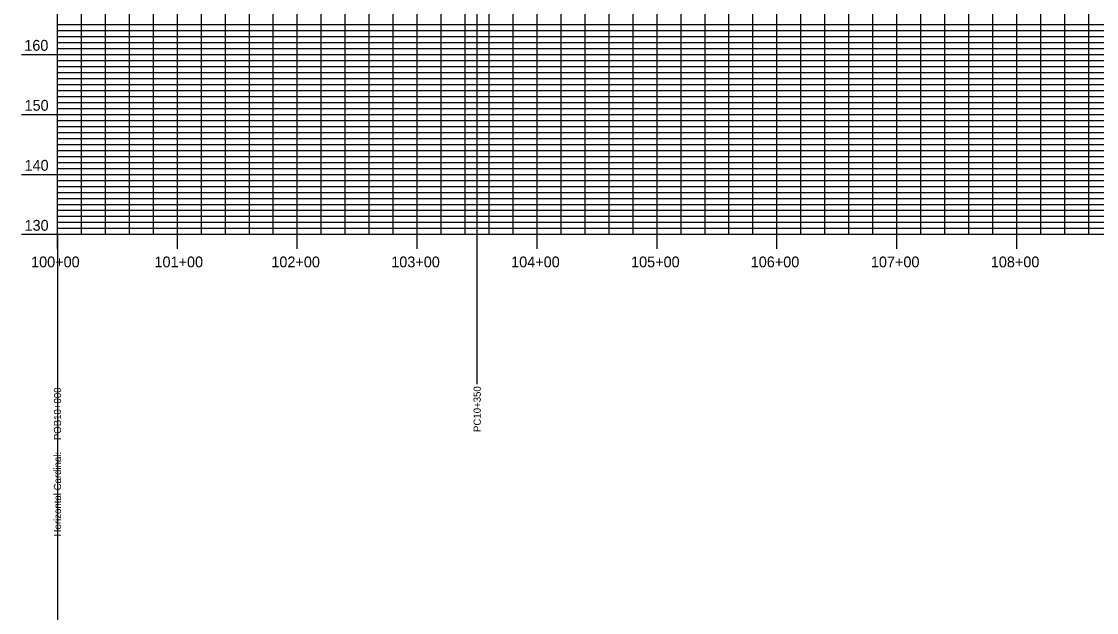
# Model space of a CAD drawing. Extents: x 1451449 to 1456010, y 297581 to 299758.
# Drawn here: x 1451450 to 1452346, y 298638 to 299131 of the extents above; entities that cross this region are included whole.
import ezdxf

# ---------------------------------------------------------------- set-up
doc = ezdxf.new("R2010")
doc.units = 0
for name, color, linetype in [('51', 7, 'Continuous'), ('Grid', 7, 'Continuous'), ('Grid_Labels', 7, 'Continuous'), ('Grid_Major', 7, 'Continuous'), ('Grid_Minor', 7, 'Continuous'), ('PCPT', 7, 'Continuous'), ('PRF_Bridge', 7, 'Continuous')]:
    doc.layers.add(name, color=color, linetype=linetype)

msp = doc.modelspace()

# ---------------------------------------------------------------- linework, layer by layer
at = {"layer": 'Grid'}
for p, q in [((1451829.67, 298828.55), (1451829.67, 299695.92)), ((1451479.67, 298953.55), (1451479.67, 299553.55)), ((1451479.67, 299128.55), (1451482.67, 299128.55)), ((1451479.67, 299123.55), (1451482.67, 299123.55)), ((1451479.67, 299118.55), (1451482.67, 299118.55)), ((1451479.67, 299113.55), (1451482.67, 299113.55)), ((1451479.67, 299108.55), (1451482.67, 299108.55)), ((1451449.67, 299103.55), (1451479.67, 299103.55)), ((1451479.67, 299098.55), (1451482.67, 299098.55)), ((1451479.67, 299093.55), (1451482.67, 299093.55)), ((1451479.67, 299088.55), (1451482.67, 299088.55)), ((1451479.67, 299083.55), (1451482.67, 299083.55)), ((1451479.67, 299078.55), (1451482.67, 299078.55)), ((1451479.67, 299073.55), (1451482.67, 299073.55)), ((1451479.67, 299068.55), (1451482.67, 299068.55)), ((1451479.67, 299063.55), (1451482.67, 299063.55)), ((1451449.67, 299053.55), (1451479.67, 299053.55)), ((1451479.67, 299058.55), (1451482.67, 299058.55)), ((1451479.67, 299048.55), (1451482.67, 299048.55)), ((1451479.67, 299043.55), (1451482.67, 299043.55)), ((1451479.67, 299038.55), (1451482.67, 299038.55)), ((1451479.67, 299033.55), (1451482.67, 299033.55)), ((1451479.67, 299028.55), (1451482.67, 299028.55)), ((1451479.67, 299023.55), (1451482.67, 299023.55)), ((1451479.67, 299018.55), (1451482.67, 299018.55)), ((1451479.67, 299013.55), (1451482.67, 299013.55)), ((1451479.67, 299008.55), (1451482.67, 299008.55)), ((1451449.67, 299003.55), (1451479.67, 299003.55)), ((1451479.67, 298998.55), (1451482.67, 298998.55)), ((1451479.67, 298993.55), (1451482.67, 298993.55)), ((1451479.67, 298988.55), (1451482.67, 298988.55)), ((1451479.67, 298983.55), (1451482.67, 298983.55)), ((1451479.67, 298978.55), (1451482.67, 298978.55)), ((1451479.67, 298973.55), (1451482.67, 298973.55)), ((1451479.67, 298968.55), (1451482.67, 298968.55)), ((1451479.67, 298963.55), (1451482.67, 298963.55)), ((1451449.67, 298953.55), (1451479.67, 298953.55)), ((1451479.67, 298958.55), (1451482.67, 298958.55)), ((1451479.67, 298953.55), (1455979.67, 298953.55)), ((1451479.67, 298941.55), (1451479.67, 298953.55)), ((1451579.67, 298941.55), (1451579.67, 298953.55)), ((1451679.67, 298941.55), (1451679.67, 298953.55)), ((1451779.67, 298941.55), (1451779.67, 298953.55)), ((1451879.67, 298941.55), (1451879.67, 298953.55)), ((1451979.67, 298941.55), (1451979.67, 298953.55)), ((1452079.67, 298941.55), (1452079.67, 298953.55)), ((1452179.67, 298941.55), (1452179.67, 298953.55)), ((1452279.67, 298941.55), (1452279.67, 298953.55))]:
    msp.add_line(p, q, dxfattribs=at)
at = {"layer": 'Grid_Major'}
for p, q in [((1451579.67, 298953.55), (1451579.67, 299553.55)), ((1451679.67, 298953.55), (1451679.67, 299553.55)), ((1451779.67, 298953.55), (1451779.67, 299553.55)), ((1451879.67, 298953.55), (1451879.67, 299553.55)), ((1451979.67, 298953.55), (1451979.67, 299553.55)), ((1452079.67, 298953.55), (1452079.67, 299553.55)), ((1452179.67, 298953.55), (1452179.67, 299553.55)), ((1452279.67, 298953.55), (1452279.67, 299553.55)), ((1451479.67, 299103.55), (1455979.67, 299103.55)), ((1451479.67, 299053.55), (1455979.67, 299053.55)), ((1451479.67, 299003.55), (1455979.67, 299003.55))]:
    msp.add_line(p, q, dxfattribs=at)
at = {"layer": 'Grid_Minor'}
for p, q in [((1451499.67, 298953.55), (1451499.67, 299553.55)), ((1451519.67, 298953.55), (1451519.67, 299553.55)), ((1451539.67, 298953.55), (1451539.67, 299553.55)), ((1451559.67, 298953.55), (1451559.67, 299553.55)), ((1451599.67, 298953.55), (1451599.67, 299553.55)), ((1451619.67, 298953.55), (1451619.67, 299553.55)), ((1451639.67, 298953.55), (1451639.67, 299553.55)), ((1451659.67, 298953.55), (1451659.67, 299553.55)), ((1451699.67, 298953.55), (1451699.67, 299553.55)), ((1451719.67, 298953.55), (1451719.67, 299553.55)), ((1451739.67, 298953.55), (1451739.67, 299553.55)), ((1451759.67, 298953.55), (1451759.67, 299553.55)), ((1451799.67, 298953.55), (1451799.67, 299553.55)), ((1451819.67, 298953.55), (1451819.67, 299553.55)), ((1451839.67, 298953.55), (1451839.67, 299553.55)), ((1451859.67, 298953.55), (1451859.67, 299553.55)), ((1451899.67, 298953.55), (1451899.67, 299553.55)), ((1451919.67, 298953.55), (1451919.67, 299553.55)), ((1451939.67, 298953.55), (1451939.67, 299553.55)), ((1451959.67, 298953.55), (1451959.67, 299553.55)), ((1451999.67, 298953.55), (1451999.67, 299553.55)), ((1452019.67, 298953.55), (1452019.67, 299553.55)), ((1452039.67, 298953.55), (1452039.67, 299553.55)), ((1452059.67, 298953.55), (1452059.67, 299553.55)), ((1452099.67, 298953.55), (1452099.67, 299553.55)), ((1452119.67, 298953.55), (1452119.67, 299553.55)), ((1452139.67, 298953.55), (1452139.67, 299553.55)), ((1452159.67, 298953.55), (1452159.67, 299553.55)), ((1452199.67, 298953.55), (1452199.67, 299553.55)), ((1452219.67, 298953.55), (1452219.67, 299553.55)), ((1452239.67, 298953.55), (1452239.67, 299553.55)), ((1452259.67, 298953.55), (1452259.67, 299553.55)), ((1452299.67, 298953.55), (1452299.67, 299553.55)), ((1452319.67, 298953.55), (1452319.67, 299553.55)), ((1452339.67, 298953.55), (1452339.67, 299553.55)), ((1451479.67, 299128.55), (1455979.67, 299128.55)), ((1451479.67, 299123.55), (1455979.67, 299123.55)), ((1451479.67, 299118.55), (1455979.67, 299118.55)), ((1451479.67, 299113.55), (1455979.67, 299113.55)), ((1451479.67, 299108.55), (1455979.67, 299108.55)), ((1451479.67, 299098.55), (1455979.67, 299098.55)), ((1451479.67, 299093.55), (1455979.67, 299093.55)), ((1451479.67, 299088.55), (1455979.67, 299088.55)), ((1451479.67, 299083.55), (1455979.67, 299083.55)), ((1451479.67, 299078.55), (1455979.67, 299078.55)), ((1451479.67, 299073.55), (1455979.67, 299073.55)), ((1451479.67, 299068.55), (1455979.67, 299068.55)), ((1451479.67, 299063.55), (1455979.67, 299063.55)), ((1451479.67, 299058.55), (1455979.67, 299058.55)), ((1451479.67, 299048.55), (1455979.67, 299048.55)), ((1451479.67, 299043.55), (1455979.67, 299043.55)), ((1451479.67, 299038.55), (1455979.67, 299038.55)), ((1451479.67, 299033.55), (1455979.67, 299033.55)), ((1451479.67, 299028.55), (1455979.67, 299028.55)), ((1451479.67, 299023.55), (1455979.67, 299023.55)), ((1451479.67, 299018.55), (1455979.67, 299018.55)), ((1451479.67, 299013.55), (1455979.67, 299013.55)), ((1451479.67, 299008.55), (1455979.67, 299008.55)), ((1451479.67, 298998.55), (1455979.67, 298998.55)), ((1451479.67, 298993.55), (1455979.67, 298993.55)), ((1451479.67, 298988.55), (1455979.67, 298988.55)), ((1451479.67, 298983.55), (1455979.67, 298983.55)), ((1451479.67, 298978.55), (1455979.67, 298978.55)), ((1451479.67, 298973.55), (1455979.67, 298973.55)), ((1451479.67, 298968.55), (1455979.67, 298968.55)), ((1451479.67, 298963.55), (1455979.67, 298963.55)), ((1451479.67, 298958.55), (1455979.67, 298958.55))]:
    msp.add_line(p, q, dxfattribs=at)
at = {"layer": 'PRF_Bridge'}
msp.add_line((1451479.67, 298953.55), (1451479.67, 297608.55), dxfattribs=at)

# ---------------------------------------------------------------- texts
at = {"layer": '51'}
msp.add_text('-', height=0.0001, dxfattribs=at).set_placement((1451479.67, 298953.55))
at = {"layer": 'Grid_Labels'}
for s, p in [('160', (1451451.99, 299106.55)), ('150', (1451452.2, 299056.55)), ('140', (1451452.2, 299006.55)), ('130', (1451452.2, 298956.55)), ('100+00', (1451457.66, 298926.05)), ('101+00', (1451560.57, 298926.05)), ('102+00', (1451658.02, 298926.05)), ('103+00', (1451758.02, 298926.05)), ('104+00', (1451858.02, 298926.05)), ('105+00', (1451958.02, 298926.05)), ('106+00', (1452057.8, 298926.05)), ('107+00', (1452158.02, 298926.05)), ('108+00', (1452258.02, 298926.05))]:
    msp.add_text(s, height=9, dxfattribs=at).set_placement(p)
at = {"layer": 'PCPT'}
for s, p in [('PC10+350', (1451832.67, 298788.81)), ('POB10+000', (1451482.67, 298782.01)), (' Horizontal Cardinal: ', (1451482.67, 298699.56))]:
    msp.add_text(s, height=6, rotation=90, dxfattribs=at).set_placement(p)

doc.saveas('drawing.dxf')
